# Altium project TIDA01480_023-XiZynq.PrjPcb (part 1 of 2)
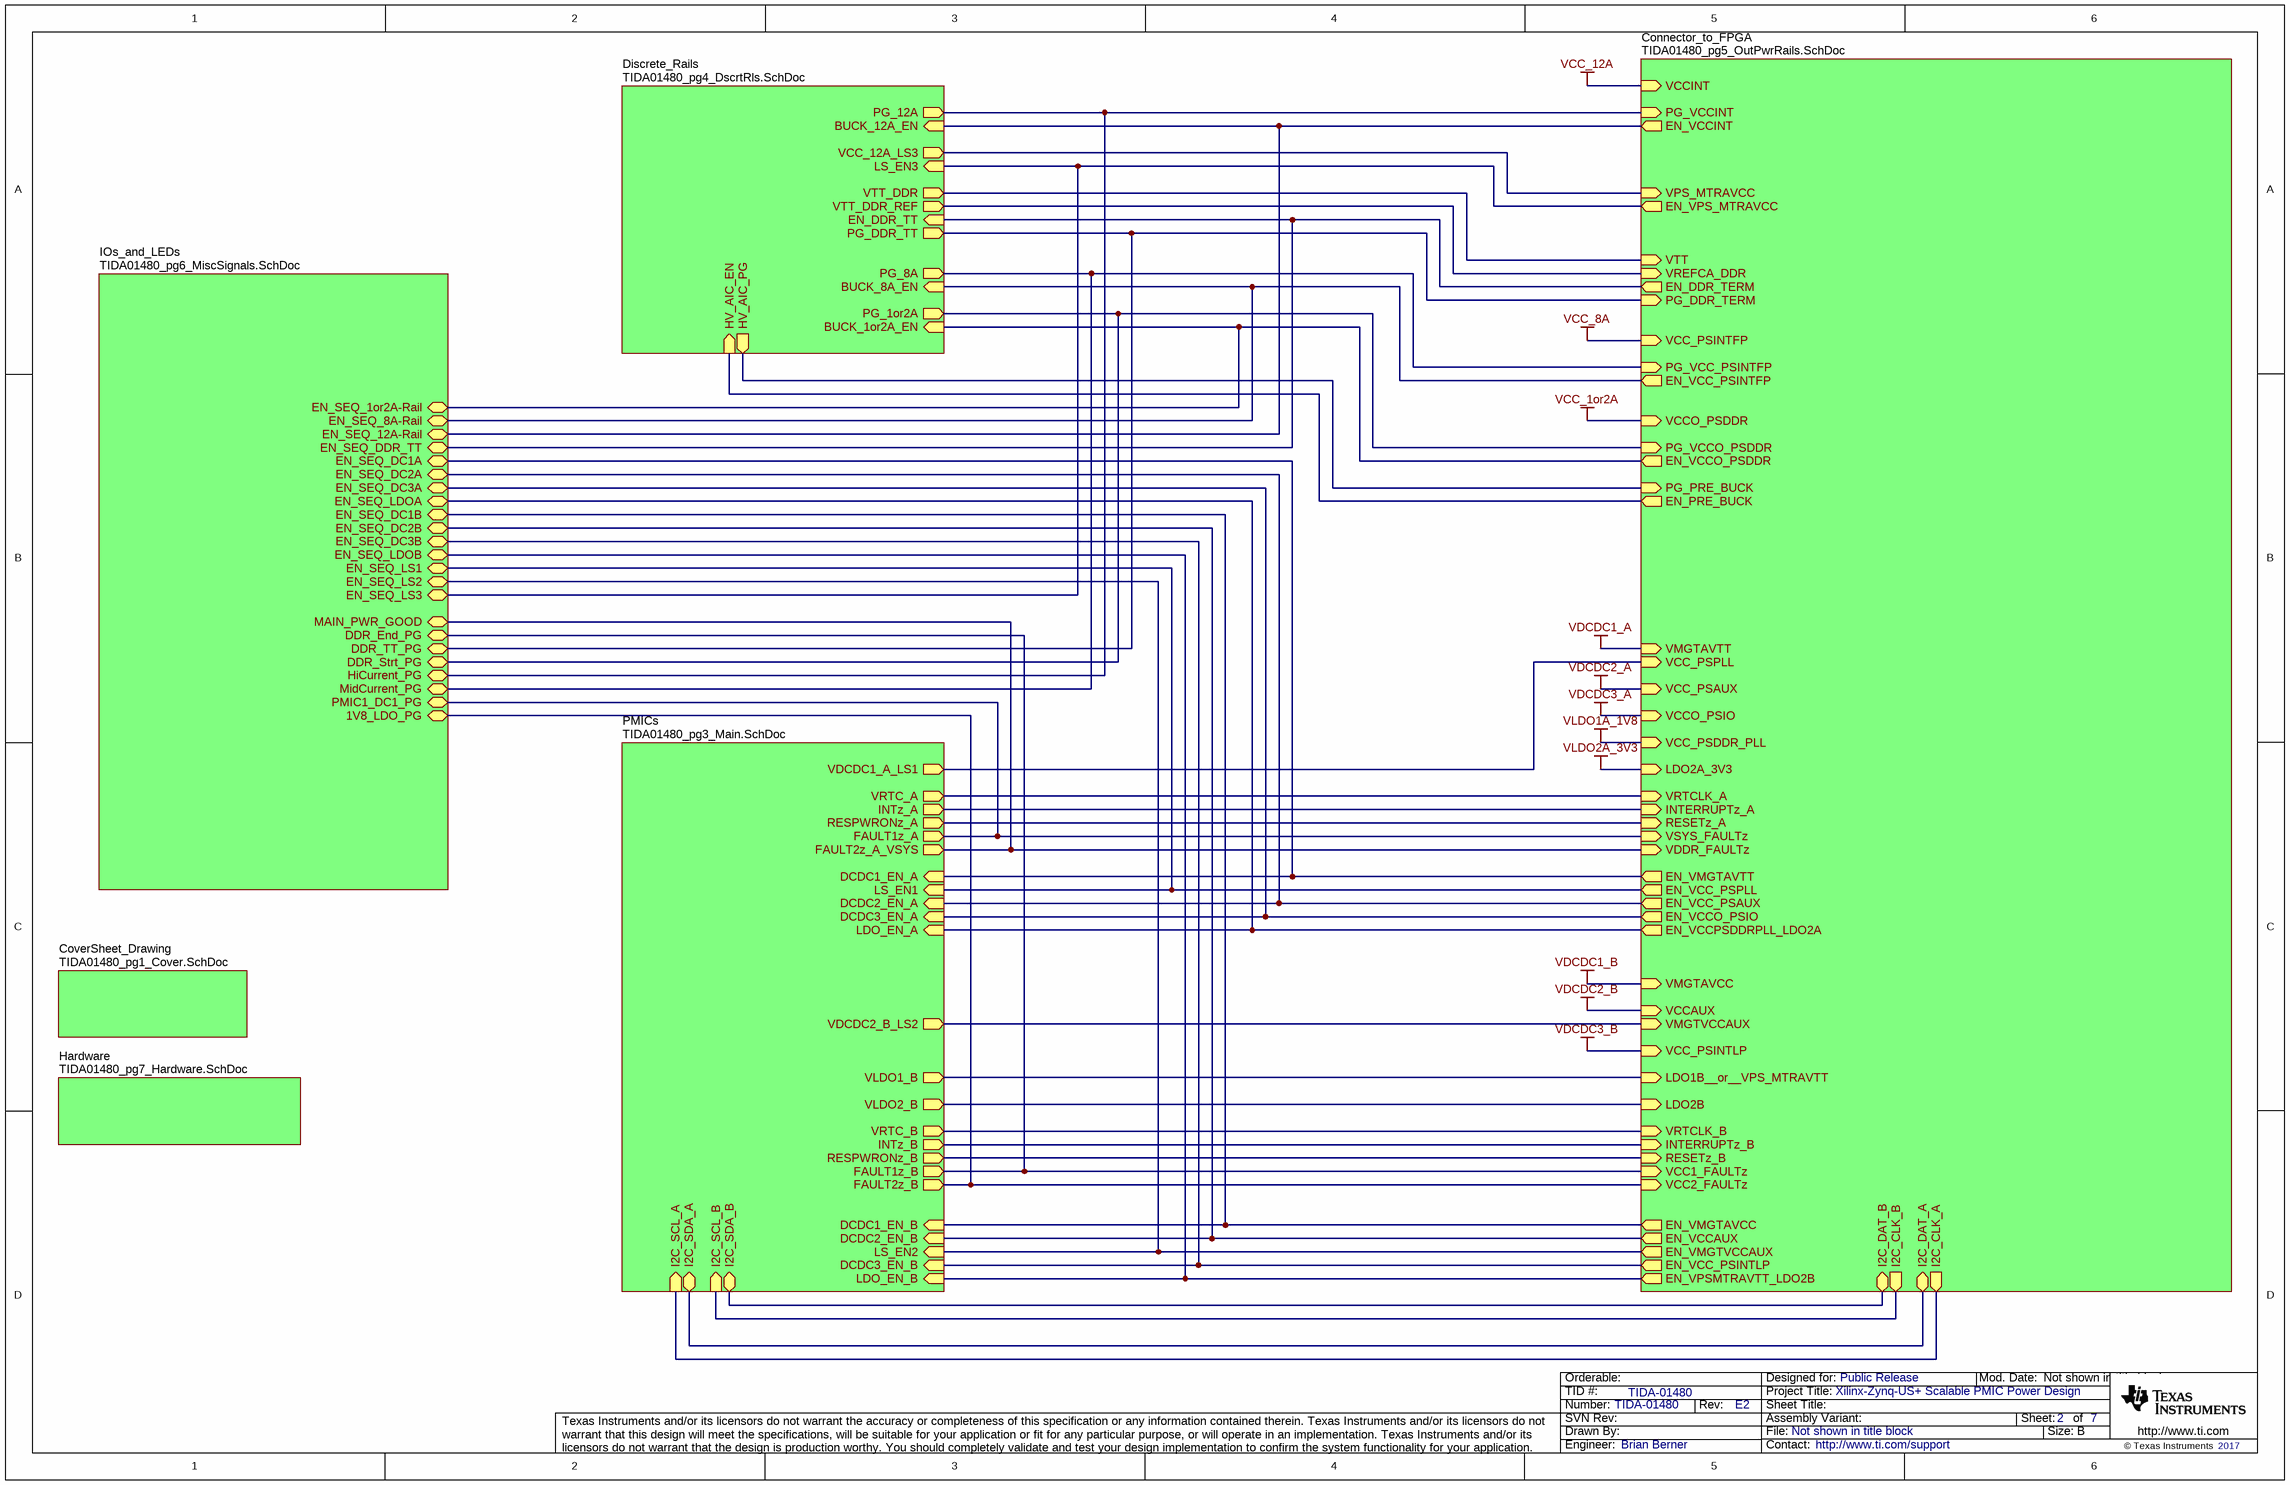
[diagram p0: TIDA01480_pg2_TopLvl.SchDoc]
CopyrightYear: 2017; PCB_Layout: Brian Berner; PCB_Rev: E2; PRJ_Customer: Public Release; PRJ_Engineer: Brian Berner; PRJ_Number: TIDA-01480; PRJ_Title: Xilinx-Zynq-US+ Scalable PMIC Power Design; SCH_Rev: E2; TechSupport: http://www.ti.com/support; TID: TIDA-01480
7 sheets, 333 parts. Net scope: hierarchical (ports join the sheet entries above them; power ports are global).
Board file: TIDA01480_PCB.PcbDoc
Sheets:
  TIDA01480_pg2_TopLvl.SchDoc
    PMICs = TIDA01480_pg3_Main.SchDoc
    Connector_to_FPGA = TIDA01480_pg5_OutPwrRails.SchDoc
    Discrete_Rails = TIDA01480_pg4_DscrtRls.SchDoc
    Hardware = TIDA01480_pg7_Hardware.SchDoc
    CoverSheet_Drawing = TIDA01480_pg1_Cover.SchDoc
    IOs_and_LEDs = TIDA01480_pg6_MiscSignals.SchDoc

## Sheet TIDA01480_pg2_TopLvl.SchDoc
size 431 x 279 mm; Date: Not shown in title block; ApprovedBy: Not shown in title block; CheckedBy: Not shown in title block; Author: Not shown in title block; CompanyName: Not shown in title block; Engineer: Not shown in title block; Organization: Not shown in title block; Address1: Not shown in title block; Address2: Not shown in title block; Address3: Not shown in title block; Address4: Not shown in title block; DocumentNumber: 1; Revision: Use project parameter SCH_Rev; SheetNumber: 2; SheetTotal: 7; PageSetup: Record=PageOptions¦CenterHorizontal=True¦CenterVertical=True¦PrintScale=1.00¦XCorrection=1.00¦YCorrection=1.00¦PrintKind=0¦BorderSize=5000000¦LeftOffset=0¦BottomOffset=0¦Orientation=2¦PaperLength=1000¦PaperWidth=1000¦Scale=100¦PaperSource=15¦PrintQuality=600¦MediaType=1¦DitherType=10¦PaperKind=Letter¦PrintScaleMode=1

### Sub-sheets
Connector_to_FPGA = TIDA01480_pg5_OutPwrRails.SchDoc: VCCINT (in), PG_VCCINT (in), VPS_MTRAVCC (in), VCC_PSINTFP (in), PG_VCC_PSINTFP (in), VCCO_PSDDR (in), PG_VCCO_PSDDR (in), VMGTAVTT (in), VCC_PSPLL (in), VCC_PSAUX (in), VCCO_PSIO (in), VCC_PSDDR_PLL (in), LDO2A_3V3 (in), VMGTAVCC (in), VCCAUX (in), VMGTVCCAUX (in), VCC_PSINTLP (in), LDO1B__or__VPS_MTRAVTT (in), LDO2B (in), INTERRUPTz_A (in), RESETz_A (in), VSYS_FAULTz (in), VDDR_FAULTz (in), INTERRUPTz_B (in), RESETz_B (in), VCC1_FAULTz (in), VCC2_FAULTz (in), EN_VCCINT (out), EN_VPS_MTRAVCC (out), EN_VCC_PSINTFP (out), EN_VCCO_PSDDR (out), EN_VMGTAVTT (out), EN_VCC_PSPLL (out), EN_VCC_PSAUX (out), EN_VCCPSDDRPLL_LDO2A (out), EN_VMGTAVCC (out), EN_VMGTVCCAUX (out), EN_VCCAUX (out), EN_VCC_PSINTLP (out), EN_VPSMTRAVTT_LDO2B (out), EN_VCCO_PSIO (out), VRTCLK_B (in), VRTCLK_A (in), VTT (in), VREFCA_DDR (in), EN_DDR_TERM (out), PG_DDR_TERM (in), I2C_DAT_B (bidir), I2C_CLK_B (out), I2C_DAT_A (bidir), I2C_CLK_A (out), PG_PRE_BUCK (in), EN_PRE_BUCK (out)
CoverSheet_Drawing = TIDA01480_pg1_Cover.SchDoc: no entries
Discrete_Rails = TIDA01480_pg4_DscrtRls.SchDoc: BUCK_12A_EN (in), BUCK_8A_EN (in), BUCK_1or2A_EN (in), PG_12A (out), PG_8A (out), PG_1or2A (out), VCC_12A_LS3 (out), LS_EN3 (in), VTT_DDR (out), VTT_DDR_REF (out), EN_DDR_TT (in), PG_DDR_TT (out), HV_AIC_EN (in), HV_AIC_PG (out)
Hardware = TIDA01480_pg7_Hardware.SchDoc: no entries
IOs_and_LEDs = TIDA01480_pg6_MiscSignals.SchDoc: EN_SEQ_LDOB, EN_SEQ_DC3B, EN_SEQ_DC2B, EN_SEQ_DC1B, EN_SEQ_LDOA, EN_SEQ_DC3A, EN_SEQ_DC2A, EN_SEQ_LS1, EN_SEQ_LS2, EN_SEQ_LS3, MAIN_PWR_GOOD, DDR_TT_PG, DDR_End_PG, DDR_Strt_PG, HiCurrent_PG, MidCurrent_PG, PMIC1_DC1_PG, 1V8_LDO_PG, EN_SEQ_DC1A, EN_SEQ_12A-Rail, EN_SEQ_8A-Rail, EN_SEQ_1or2A-Rail, EN_SEQ_DDR_TT
PMICs = TIDA01480_pg3_Main.SchDoc: INTz_A (out), RESPWRONz_A (out), FAULT1z_A (out), FAULT2z_A_VSYS (out), DCDC1_EN_A (in), DCDC2_EN_A (in), DCDC3_EN_A (in), LDO_EN_A (in), VLDO1_B (out), VLDO2_B (out), INTz_B (out), RESPWRONz_B (out), FAULT1z_B (out), FAULT2z_B (out), DCDC1_EN_B (in), DCDC2_EN_B (in), DCDC3_EN_B (in), LDO_EN_B (in), VDCDC1_A_LS1 (out), VDCDC2_B_LS2 (out), LS_EN1 (in), LS_EN2 (in), I2C_SCL_A (in), I2C_SDA_A (bidir), VRTC_A (out), VRTC_B (out), I2C_SCL_B (in), I2C_SDA_B (bidir)

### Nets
BUCK_1or2A_EN: sheet Connector_to_FPGA/EN_VCCO_PSDDR, sheet Discrete_Rails/BUCK_1or2A_EN, sheet IOs_and_LEDs/EN_SEQ_1or2A-Rail
BUCK_8A_EN: sheet Connector_to_FPGA/EN_VCC_PSINTFP, sheet Discrete_Rails/BUCK_8A_EN, sheet IOs_and_LEDs/EN_SEQ_8A-Rail
BUCK_12A_EN: sheet Connector_to_FPGA/EN_VCCINT, sheet Discrete_Rails/BUCK_12A_EN, sheet IOs_and_LEDs/EN_SEQ_12A-Rail
DCDC1_EN_A: sheet PMICs/DCDC1_EN_A, sheet Connector_to_FPGA/EN_VMGTAVTT, sheet IOs_and_LEDs/EN_SEQ_DC1A
DCDC1_EN_B: sheet PMICs/DCDC1_EN_B, sheet Connector_to_FPGA/EN_VMGTAVCC, sheet IOs_and_LEDs/EN_SEQ_DC1B
DCDC2_EN_A: sheet PMICs/DCDC2_EN_A, sheet Connector_to_FPGA/EN_VCC_PSAUX, sheet IOs_and_LEDs/EN_SEQ_DC2A
DCDC2_EN_B: sheet PMICs/DCDC2_EN_B, sheet Connector_to_FPGA/EN_VCCAUX, sheet IOs_and_LEDs/EN_SEQ_DC2B
DCDC3_EN_A: sheet PMICs/DCDC3_EN_A, sheet Connector_to_FPGA/EN_VCCO_PSIO, sheet IOs_and_LEDs/EN_SEQ_DC3A
DCDC3_EN_B: sheet PMICs/DCDC3_EN_B, sheet Connector_to_FPGA/EN_VCC_PSINTLP, sheet IOs_and_LEDs/EN_SEQ_DC3B
DDR_Strt_PG: sheet Connector_to_FPGA/PG_VCCO_PSDDR, sheet Discrete_Rails/PG_1or2A, sheet IOs_and_LEDs/DDR_Strt_PG
DDR_TT_PG: sheet Connector_to_FPGA/PG_DDR_TERM, sheet Discrete_Rails/PG_DDR_TT, sheet IOs_and_LEDs/DDR_TT_PG
EN_DDR_TERM: sheet Connector_to_FPGA/EN_DDR_TERM, sheet Discrete_Rails/EN_DDR_TT, sheet IOs_and_LEDs/EN_SEQ_DDR_TT
EN_PRE_BUCK: sheet Connector_to_FPGA/EN_PRE_BUCK, sheet Discrete_Rails/HV_AIC_EN
EN_SEQ_LDOA: sheet PMICs/LDO_EN_A, sheet Connector_to_FPGA/EN_VCCPSDDRPLL_LDO2A, sheet IOs_and_LEDs/EN_SEQ_LDOA
EN_SEQ_LDOB: sheet PMICs/LDO_EN_B, sheet Connector_to_FPGA/EN_VPSMTRAVTT_LDO2B, sheet IOs_and_LEDs/EN_SEQ_LDOB
EN_SEQ_LS1: sheet PMICs/LS_EN1, sheet Connector_to_FPGA/EN_VCC_PSPLL, sheet IOs_and_LEDs/EN_SEQ_LS1
EN_SEQ_LS2: sheet PMICs/LS_EN2, sheet Connector_to_FPGA/EN_VMGTVCCAUX, sheet IOs_and_LEDs/EN_SEQ_LS2
EN_SEQ_LS3: sheet Connector_to_FPGA/EN_VPS_MTRAVCC, sheet Discrete_Rails/LS_EN3, sheet IOs_and_LEDs/EN_SEQ_LS3
HiCurrent_PG: sheet Connector_to_FPGA/PG_VCCINT, sheet Discrete_Rails/PG_12A, sheet IOs_and_LEDs/HiCurrent_PG
HV_AIC_PG: sheet Connector_to_FPGA/PG_PRE_BUCK, sheet Discrete_Rails/HV_AIC_PG
I2C_CLK_A: sheet PMICs/I2C_SCL_A, sheet Connector_to_FPGA/I2C_CLK_A
I2C_CLK_B: sheet PMICs/I2C_SCL_B, sheet Connector_to_FPGA/I2C_CLK_B
I2C_DAT_A: sheet PMICs/I2C_SDA_A, sheet Connector_to_FPGA/I2C_DAT_A
I2C_DAT_B: sheet PMICs/I2C_SDA_B, sheet Connector_to_FPGA/I2C_DAT_B
INTERRUPTz_A: sheet PMICs/INTz_A, sheet Connector_to_FPGA/INTERRUPTz_A
INTERRUPTz_B: sheet PMICs/INTz_B, sheet Connector_to_FPGA/INTERRUPTz_B
LDO1B__or__VPS_MTRAVTT: sheet PMICs/VLDO1_B, sheet Connector_to_FPGA/LDO1B__or__VPS_MTRAVTT
LDO2B: sheet PMICs/VLDO2_B, sheet Connector_to_FPGA/LDO2B
LOW_BATz_A: sheet PMICs/FAULT1z_A, sheet Connector_to_FPGA/VSYS_FAULTz, sheet IOs_and_LEDs/PMIC1_DC1_PG
LOW_BATz_B: sheet PMICs/FAULT1z_B, sheet Connector_to_FPGA/VCC1_FAULTz, sheet IOs_and_LEDs/DDR_End_PG
MidCurrent_PG: sheet Connector_to_FPGA/PG_VCC_PSINTFP, sheet Discrete_Rails/PG_8A, sheet IOs_and_LEDs/MidCurrent_PG
PWRFAILz_A: sheet PMICs/FAULT2z_A_VSYS, sheet Connector_to_FPGA/VDDR_FAULTz, sheet IOs_and_LEDs/MAIN_PWR_GOOD
PWRFAILz_B: sheet PMICs/FAULT2z_B, sheet Connector_to_FPGA/VCC2_FAULTz, sheet IOs_and_LEDs/1V8_LDO_PG
RESETz_A: sheet PMICs/RESPWRONz_A, sheet Connector_to_FPGA/RESETz_A
RESETz_B: sheet PMICs/RESPWRONz_B, sheet Connector_to_FPGA/RESETz_B
VCC_12A_LS3: sheet Connector_to_FPGA/VPS_MTRAVCC, sheet Discrete_Rails/VCC_12A_LS3
VCC_PSPLL: sheet PMICs/VDCDC1_A_LS1, sheet Connector_to_FPGA/VCC_PSPLL
VDCDC2_B_LS2: sheet PMICs/VDCDC2_B_LS2, sheet Connector_to_FPGA/VMGTVCCAUX
VREFCA_DDR: sheet Connector_to_FPGA/VREFCA_DDR, sheet Discrete_Rails/VTT_DDR_REF
VRTC_A: sheet PMICs/VRTC_A, sheet Connector_to_FPGA/VRTCLK_A
VRTC_B: sheet PMICs/VRTC_B, sheet Connector_to_FPGA/VRTCLK_B
VTT: sheet Connector_to_FPGA/VTT, sheet Discrete_Rails/VTT_DDR

## Sheet TIDA01480_pg3_Main.SchDoc
size 431 x 279 mm; Date: Not shown in title block; ApprovedBy: Not shown in title block; CheckedBy: Not shown in title block; Author: Not shown in title block; CompanyName: Not shown in title block; Engineer: Not shown in title block; Organization: Not shown in title block; Address1: Not shown in title block; Address2: Not shown in title block; Address3: Not shown in title block; Address4: Not shown in title block; DocumentNumber: 1; Revision: Use project parameter SCH_Rev; SheetNumber: 3; SheetTotal: 7; PageSetup: Record=PageOptions¦CenterHorizontal=True¦CenterVertical=True¦PrintScale=1.00¦XCorrection=1.00¦YCorrection=1.00¦PrintKind=0¦BorderSize=5000000¦LeftOffset=0¦BottomOffset=0¦Orientation=2¦PaperLength=1000¦PaperWidth=1000¦Scale=100¦PaperSource=15¦PrintQuality=600¦MediaType=1¦DitherType=10¦PaperKind=Letter¦PrintScaleMode=1
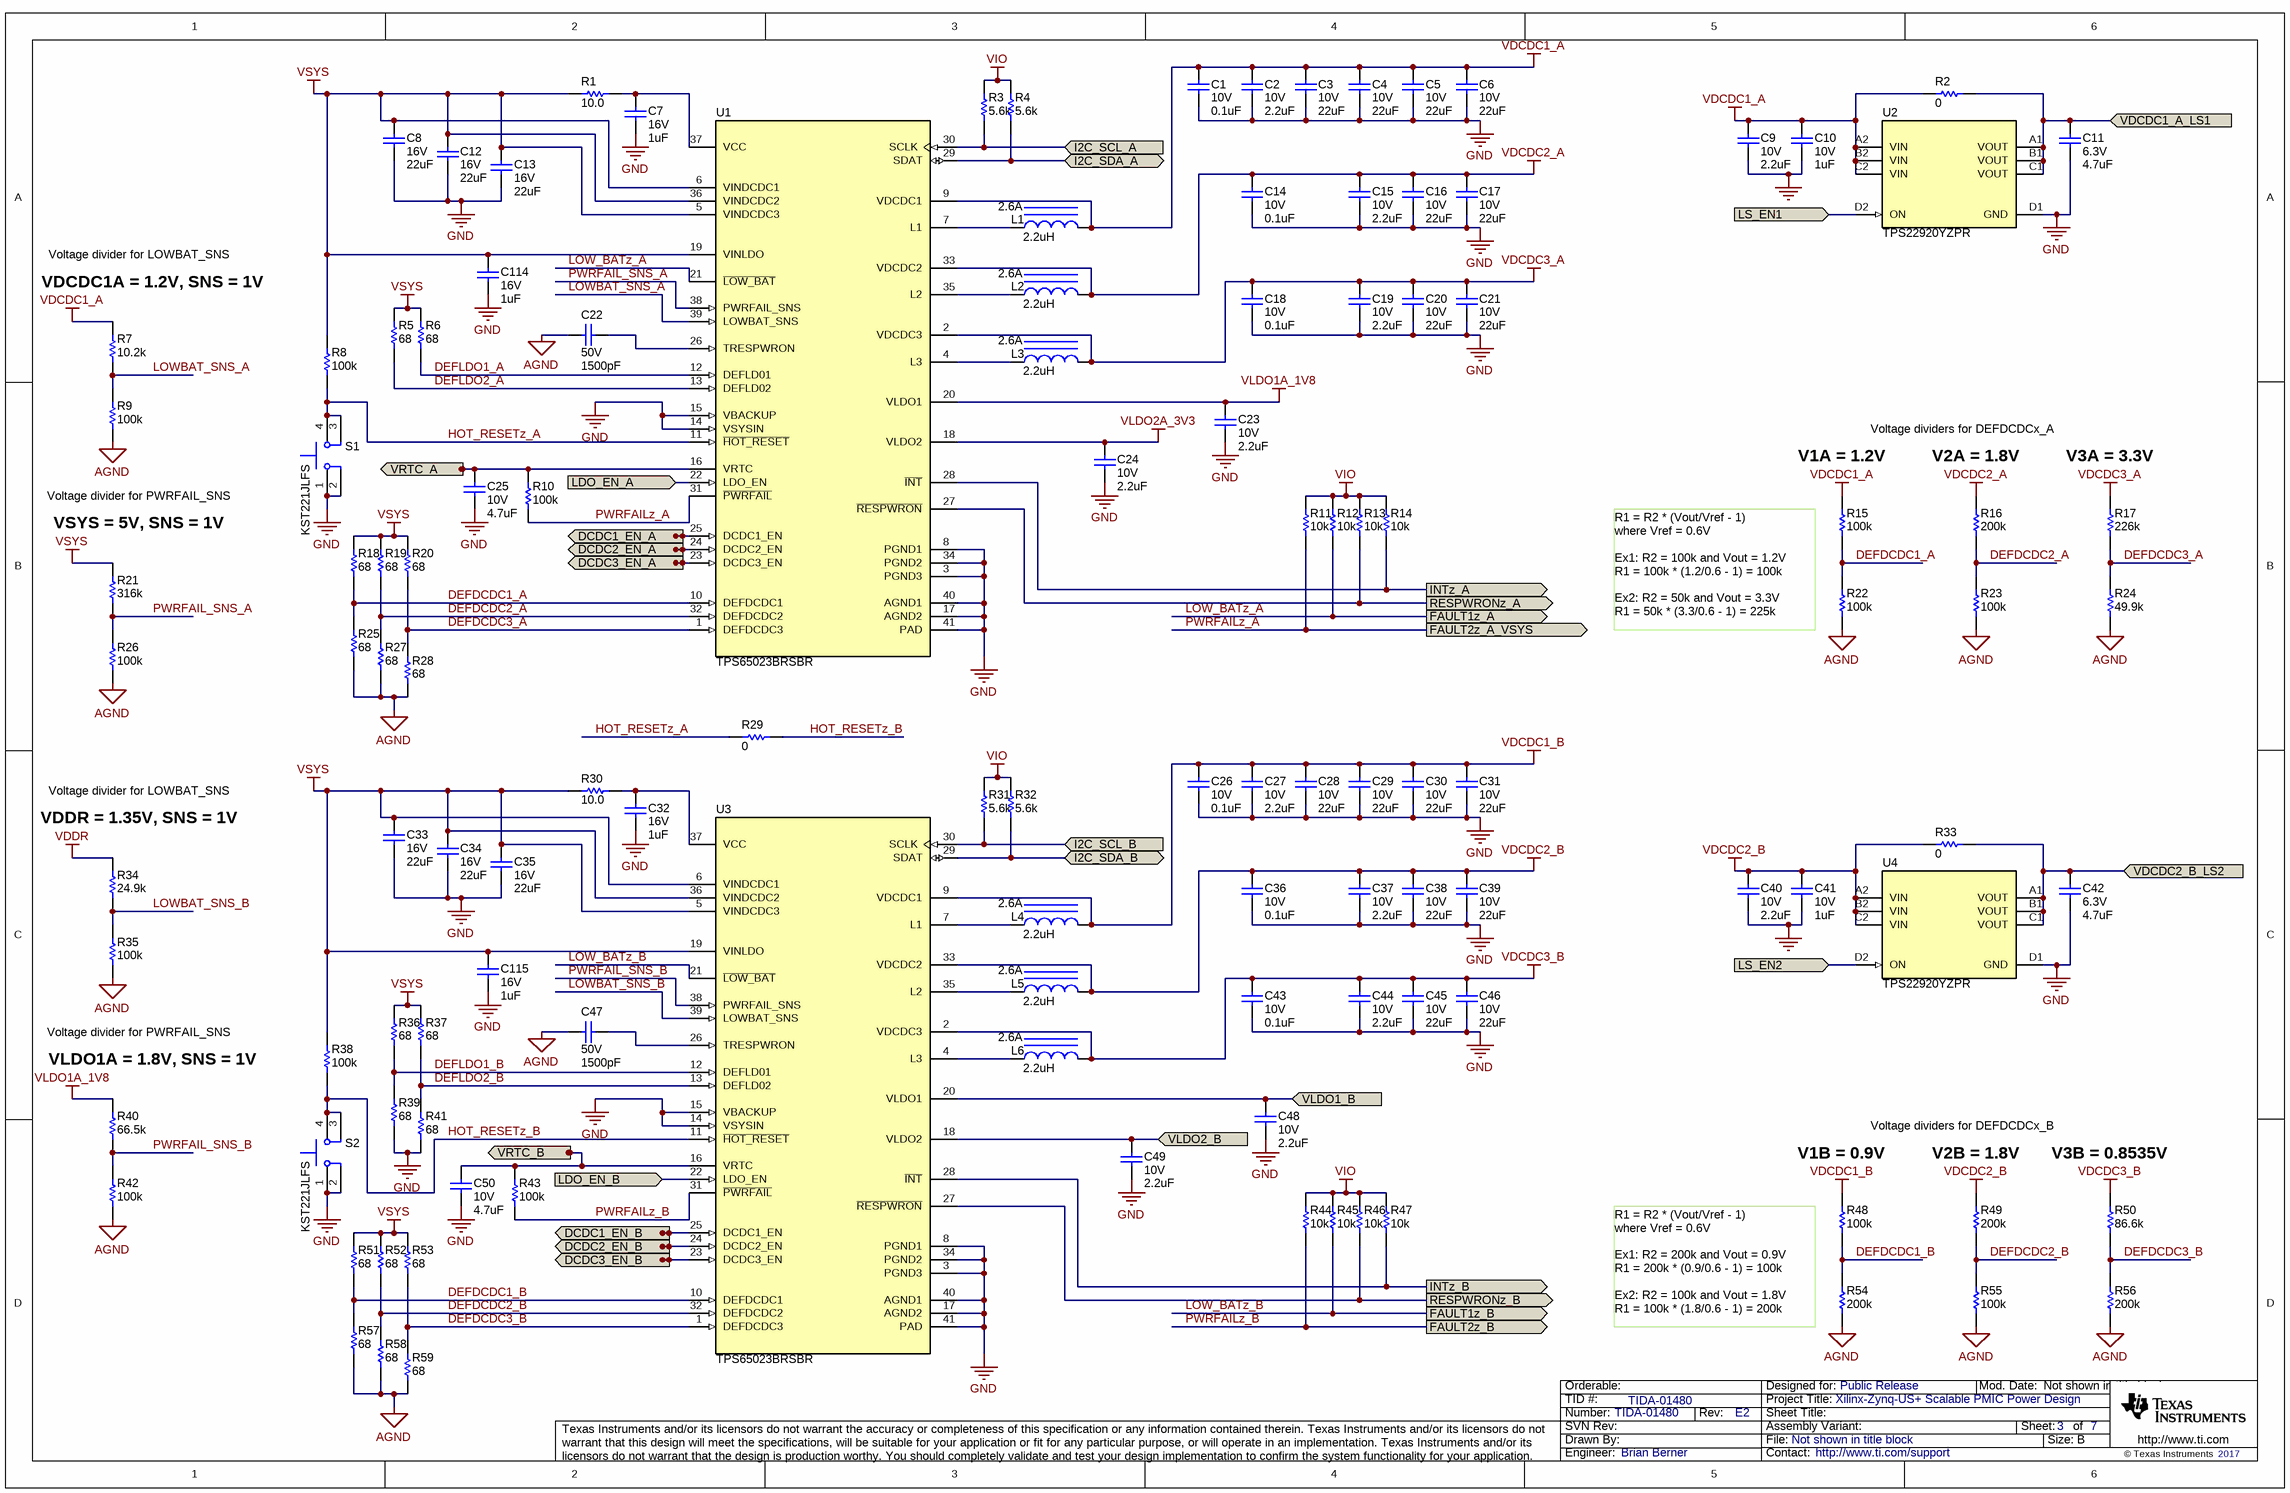
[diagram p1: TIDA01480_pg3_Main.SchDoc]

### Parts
C1  VDC_V: 10V  ValueDisplayed: 0.1uF  [0402]  (hidden comment: GRM155R71A104KA01D)
C2  VDC_V: 10V  ValueDisplayed: 2.2uF  [0603]  (hidden comment: GRM188R71A225KE15D)
C3  VDC_V: 10V  ValueDisplayed: 22uF  [0805_HV]  (hidden comment: C2012X7S1A226M125AC)
C4  VDC_V: 10V  ValueDisplayed: 22uF  [0805_HV]  (hidden comment: C2012X7S1A226M125AC)
C5  VDC_V: 10V  ValueDisplayed: 22uF  [0805_HV]  (hidden comment: C2012X7S1A226M125AC)
C6  VDC_V: 10V  ValueDisplayed: 22uF  [0805_HV]  (hidden comment: C2012X7S1A226M125AC)
C7  VDC_V: 16V  ValueDisplayed: 1uF  [0603]  (hidden comment: 885012106017)
C8  VDC_V: 16V  ValueDisplayed: 22uF  [1210_280]  (hidden comment: C3225X7R1C226K250AC)
C9  VDC_V: 10V  ValueDisplayed: 2.2uF  [0603]  (hidden comment: GRM188R71A225KE15D)
C10  VDC_V: 10V  ValueDisplayed: 1uF  [0402]  (hidden comment: GRM155R61A105ME15D)
C11  VDC_V: 6.3V  ValueDisplayed: 4.7uF  [0603]  (hidden comment: JMK107BB7475MA-T)
C12  VDC_V: 16V  ValueDisplayed: 22uF  [1210_280]  (hidden comment: C3225X7R1C226K250AC)
C13  VDC_V: 16V  ValueDisplayed: 22uF  [1210_280]  (hidden comment: C3225X7R1C226K250AC)
C14  VDC_V: 10V  ValueDisplayed: 0.1uF  [0402]  (hidden comment: GRM155R71A104KA01D)
C15  VDC_V: 10V  ValueDisplayed: 2.2uF  [0603]  (hidden comment: GRM188R71A225KE15D)
C16  VDC_V: 10V  ValueDisplayed: 22uF  [0805_HV]  (hidden comment: C2012X7S1A226M125AC)
C17  VDC_V: 10V  ValueDisplayed: 22uF  [0805_HV]  (hidden comment: C2012X7S1A226M125AC)
C18  VDC_V: 10V  ValueDisplayed: 0.1uF  [0402]  (hidden comment: GRM155R71A104KA01D)
C19  VDC_V: 10V  ValueDisplayed: 2.2uF  [0603]  (hidden comment: GRM188R71A225KE15D)
C20  VDC_V: 10V  ValueDisplayed: 22uF  [0805_HV]  (hidden comment: C2012X7S1A226M125AC)
C21  VDC_V: 10V  ValueDisplayed: 22uF  [0805_HV]  (hidden comment: C2012X7S1A226M125AC)
C22  VDC_V: 50V  ValueDisplayed: 1500pF  [0402]  (hidden comment: GRM155R71H152KA01D)
C23  VDC_V: 10V  ValueDisplayed: 2.2uF  [0603]  (hidden comment: GRM188R71A225KE15D)
C24  VDC_V: 10V  ValueDisplayed: 2.2uF  [0603]  (hidden comment: GRM188R71A225KE15D)
C25  VDC_V: 10V  ValueDisplayed: 4.7uF  [0805_HV]  (hidden comment: 885012207025)
C26  VDC_V: 10V  ValueDisplayed: 0.1uF  [0402]  (hidden comment: GRM155R71A104KA01D)
C27  VDC_V: 10V  ValueDisplayed: 2.2uF  [0603]  (hidden comment: GRM188R71A225KE15D)
C28  VDC_V: 10V  ValueDisplayed: 22uF  [0805_HV]  (hidden comment: C2012X7S1A226M125AC)
C29  VDC_V: 10V  ValueDisplayed: 22uF  [0805_HV]  (hidden comment: C2012X7S1A226M125AC)
C30  VDC_V: 10V  ValueDisplayed: 22uF  [0805_HV]  (hidden comment: C2012X7S1A226M125AC)
C31  VDC_V: 10V  ValueDisplayed: 22uF  [0805_HV]  (hidden comment: C2012X7S1A226M125AC)
C32  VDC_V: 16V  ValueDisplayed: 1uF  [0603]  (hidden comment: 885012106017)
C33  VDC_V: 16V  ValueDisplayed: 22uF  [1210_280]  (hidden comment: C3225X7R1C226K250AC)
C34  VDC_V: 16V  ValueDisplayed: 22uF  [1210_280]  (hidden comment: C3225X7R1C226K250AC)
C35  VDC_V: 16V  ValueDisplayed: 22uF  [1210_280]  (hidden comment: C3225X7R1C226K250AC)
C36  VDC_V: 10V  ValueDisplayed: 0.1uF  [0402]  (hidden comment: GRM155R71A104KA01D)
C37  VDC_V: 10V  ValueDisplayed: 2.2uF  [0603]  (hidden comment: GRM188R71A225KE15D)
C38  VDC_V: 10V  ValueDisplayed: 22uF  [0805_HV]  (hidden comment: C2012X7S1A226M125AC)
C39  VDC_V: 10V  ValueDisplayed: 22uF  [0805_HV]  (hidden comment: C2012X7S1A226M125AC)
C40  VDC_V: 10V  ValueDisplayed: 2.2uF  [0603]  (hidden comment: GRM188R71A225KE15D)
C41  VDC_V: 10V  ValueDisplayed: 1uF  [0402]  (hidden comment: GRM155R61A105ME15D)
C42  VDC_V: 6.3V  ValueDisplayed: 4.7uF  [0603]  (hidden comment: JMK107BB7475MA-T)
C43  VDC_V: 10V  ValueDisplayed: 0.1uF  [0402]  (hidden comment: GRM155R71A104KA01D)
C44  VDC_V: 10V  ValueDisplayed: 2.2uF  [0603]  (hidden comment: GRM188R71A225KE15D)
C45  VDC_V: 10V  ValueDisplayed: 22uF  [0805_HV]  (hidden comment: C2012X7S1A226M125AC)
C46  VDC_V: 10V  ValueDisplayed: 22uF  [0805_HV]  (hidden comment: C2012X7S1A226M125AC)
C47  VDC_V: 50V  ValueDisplayed: 1500pF  [0402]  (hidden comment: GRM155R71H152KA01D)
C48  VDC_V: 10V  ValueDisplayed: 2.2uF  [0603]  (hidden comment: GRM188R71A225KE15D)
C49  VDC_V: 10V  ValueDisplayed: 2.2uF  [0603]  (hidden comment: GRM188R71A225KE15D)
C50  VDC_V: 10V  ValueDisplayed: 4.7uF  [0805_HV]  (hidden comment: 885012207025)
C114  VDC_V: 16V  ValueDisplayed: 1uF  [0603]  (hidden comment: 885012106017)
C115  VDC_V: 16V  ValueDisplayed: 1uF  [0603]  (hidden comment: 885012106017)
L1  Imax_A: 2.6A  ValueDisplayed: 2.2uH  [TFM252012]  (hidden comment: TFM252012ALMA2R2MTAA)
L2  Imax_A: 2.6A  ValueDisplayed: 2.2uH  [TFM252012]  (hidden comment: TFM252012ALMA2R2MTAA)
L3  Imax_A: 2.6A  ValueDisplayed: 2.2uH  [TFM252012]  (hidden comment: TFM252012ALMA2R2MTAA)
L4  Imax_A: 2.6A  ValueDisplayed: 2.2uH  [TFM252012]  (hidden comment: TFM252012ALMA2R2MTAA)
L5  Imax_A: 2.6A  ValueDisplayed: 2.2uH  [TFM252012]  (hidden comment: TFM252012ALMA2R2MTAA)
L6  Imax_A: 2.6A  ValueDisplayed: 2.2uH  [TFM252012]  (hidden comment: TFM252012ALMA2R2MTAA)
R1  ValueDisplayed: 10.0  [0402]  (hidden comment: CRCW040210R0FKED)
R2  ValueDisplayed: 0  [1206]  (hidden comment: CRCW12060000Z0EA)
R3  ValueDisplayed: 5.6k  [0402]  (hidden comment: CRCW04025K60JNED)
R4  ValueDisplayed: 5.6k  [0402]  (hidden comment: CRCW04025K60JNED)
R5  ValueDisplayed: 68  [0402]  (hidden comment: CRCW040268R0JNED)
R6  ValueDisplayed: 68  [0402]  (hidden comment: CRCW040268R0JNED)
R7  ValueDisplayed: 10.2k  [0402]  (hidden comment: CRCW040210K2FKED)
R8  ValueDisplayed: 100k  [0402]  (hidden comment: CRCW0402100KJNED)
R9  ValueDisplayed: 100k  [0402]  (hidden comment: RG1005P-104-B-T5)
R10  ValueDisplayed: 100k  [0402]  (hidden comment: CRCW0402100KJNED)
R11  ValueDisplayed: 10k  [0402]  (hidden comment: CRCW040210K0JNED)
R12  ValueDisplayed: 10k  [0402]  (hidden comment: CRCW040210K0JNED)
R13  ValueDisplayed: 10k  [0402]  (hidden comment: CRCW040210K0JNED)
R14  ValueDisplayed: 10k  [0402]  (hidden comment: CRCW040210K0JNED)
R15  ValueDisplayed: 100k  [0402]  (hidden comment: RG1005P-104-B-T5)
R16  ValueDisplayed: 200k  [0402]  (hidden comment: CRCW0402200KFKED)
R17  ValueDisplayed: 226k  [0402]  (hidden comment: CRCW0402226KFKED)
R18  ValueDisplayed: 68  [0402]  (hidden comment: CRCW040268R0JNED)
R19  ValueDisplayed: 68  [0402]  (hidden comment: CRCW040268R0JNED)
R20  ValueDisplayed: 68  [0402]  (hidden comment: CRCW040268R0JNED)
R21  ValueDisplayed: 316k  [0402]  (hidden comment: CRCW0402316KFKED)
R22  ValueDisplayed: 100k  [0402]  (hidden comment: RG1005P-104-B-T5)
R23  ValueDisplayed: 100k  [0402]  (hidden comment: RG1005P-104-B-T5)
R24  ValueDisplayed: 49.9k  [0402]  (hidden comment: ERJ-2RKF4992X)
R25  ValueDisplayed: 68  [0402]  (hidden comment: CRCW040268R0JNED)
R26  ValueDisplayed: 100k  [0402]  (hidden comment: RG1005P-104-B-T5)
R27  ValueDisplayed: 68  [0402]  (hidden comment: CRCW040268R0JNED)
R28  ValueDisplayed: 68  [0402]  (hidden comment: CRCW040268R0JNED)
R29  ValueDisplayed: 0  [0402]  (hidden comment: CRCW04020000Z0ED)
R30  ValueDisplayed: 10.0  [0402]  (hidden comment: CRCW040210R0FKED)
R31  ValueDisplayed: 5.6k  [0402]  (hidden comment: CRCW04025K60JNED)
R32  ValueDisplayed: 5.6k  [0402]  (hidden comment: CRCW04025K60JNED)
R33  ValueDisplayed: 0  [1206]  (hidden comment: CRCW12060000Z0EA)
R34  ValueDisplayed: 24.9k  [0402]  (hidden comment: CRCW040224K9FKED)
R35  ValueDisplayed: 100k  [0402]  (hidden comment: RG1005P-104-B-T5)
R36  ValueDisplayed: 68  [0402]  (hidden comment: CRCW040268R0JNED)
R37  ValueDisplayed: 68  [0402]  (hidden comment: CRCW040268R0JNED)
R38  ValueDisplayed: 100k  [0402]  (hidden comment: CRCW0402100KJNED)
R39  ValueDisplayed: 68  [0402]  (hidden comment: CRCW040268R0JNED)
R40  ValueDisplayed: 66.5k  [0402]  (hidden comment: CRCW040266K5FKED)
R41  ValueDisplayed: 68  [0402]  (hidden comment: CRCW040268R0JNED)
R42  ValueDisplayed: 100k  [0402]  (hidden comment: RG1005P-104-B-T5)
R43  ValueDisplayed: 100k  [0402]  (hidden comment: CRCW0402100KJNED)
R44  ValueDisplayed: 10k  [0402]  (hidden comment: CRCW040210K0JNED)
R45  ValueDisplayed: 10k  [0402]  (hidden comment: CRCW040210K0JNED)
R46  ValueDisplayed: 10k  [0402]  (hidden comment: CRCW040210K0JNED)
R47  ValueDisplayed: 10k  [0402]  (hidden comment: CRCW040210K0JNED)
R48  ValueDisplayed: 100k  [0402]  (hidden comment: RG1005P-104-B-T5)
R49  ValueDisplayed: 200k  [0402]  (hidden comment: CRCW0402200KFKED)
R50  ValueDisplayed: 86.6k  [0402]  (hidden comment: ERA-2AEB8662X)
R51  ValueDisplayed: 68  [0402]  (hidden comment: CRCW040268R0JNED)
R52  ValueDisplayed: 68  [0402]  (hidden comment: CRCW040268R0JNED)
R53  ValueDisplayed: 68  [0402]  (hidden comment: CRCW040268R0JNED)
R54  ValueDisplayed: 200k  [0402]  (hidden comment: CRCW0402200KFKED)
R55  ValueDisplayed: 100k  [0402]  (hidden comment: RG1005P-104-B-T5)
R56  ValueDisplayed: 200k  [0402]  (hidden comment: CRCW0402200KFKED)
R57  ValueDisplayed: 68  [0402]  (hidden comment: CRCW040268R0JNED)
R58  ValueDisplayed: 68  [0402]  (hidden comment: CRCW040268R0JNED)
R59  ValueDisplayed: 68  [0402]  (hidden comment: CRCW040268R0JNED)
S1  KST221JLFS  [SW_KST221JLFS]
S2  KST221JLFS  [SW_KST221JLFS]
U1  TPS65023BRSBR  [RSB0040B]
U2  TPS22920YZPR  [YZP0008ADCD]
U3  TPS65023BRSBR  [RSB0040B]
U4  TPS22920YZPR  [YZP0008ADCD]

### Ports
DCDC1_EN_A (in), DCDC1_EN_B (in), DCDC2_EN_A (in), DCDC2_EN_B (in), DCDC3_EN_A (in), DCDC3_EN_B (in), FAULT1z_A (out), FAULT1z_B (out), FAULT2z_A_VSYS (out), FAULT2z_B (out), I2C_SCL_A (in), I2C_SCL_B (in), I2C_SDA_A (bidir), I2C_SDA_B (bidir), INTz_A (out), INTz_B (out), LDO_EN_A (in), LDO_EN_B (in), LS_EN1 (in), LS_EN2 (in), RESPWRONz_A (out), RESPWRONz_B (out), VDCDC1_A_LS1, VDCDC2_B_LS2, VLDO1_B, VLDO2_B, VRTC_A, VRTC_B

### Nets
AGND: C22.2 C47.2 R9.1 R22.1 R23.1 R24.1 R25.1 R26.1 R27.1 R28.1 R35.1 R42.1 R54.1 R55.1 R56.1 R57.1 R58.1 R59.1
GND: C1.2 C2.2 C3.2 C4.2 C5.2 C6.2 C7.2 C8.2 C9.2 C10.2 C11.2 C12.2 C13.2 C14.2 C15.2 C16.2 C17.2 C18.2 C19.2 C20.2 C21.2 C23.2 C24.2 C25.2 C26.2 C27.2 C28.2 C29.2 C30.2 C31.2 C32.2 C33.2 C34.2 C35.2 C36.2 C37.2 C38.2 C39.2 C40.2 C41.2 C42.2 C43.2 C44.2 C45.2 C46.2 C48.2 C49.2 C50.2 C114.2 C115.2 R39.1 R41.1 S1.1 S1.2 S2.1 S2.2 U1.3(PGND3) U1.8(PGND1) U1.14(VSYSIN) U1.15(VBACKUP) U1.17(AGND2) U1.34(PGND2) U1.40(AGND1) U1.41(PAD) U2.D1(GND) U3.3(PGND3) U3.8(PGND1) U3.14(VSYSIN) U3.15(VBACKUP) U3.17(AGND2) U3.34(PGND2) U3.40(AGND1) U3.41(PAD) U4.D1(GND)
VDCDC1_A: C1.1 C2.1 C3.1 C4.1 C5.1 C6.1 C9.1 C10.1 L1.2 R2.1 R7.2 R15.2 U1.9(VDCDC1) U2.A2(VIN) U2.B2(VIN) U2.C2(VIN)
VDCDC1_B: C26.1 C27.1 C28.1 C29.1 C30.1 C31.1 L4.2 R48.2 U3.9(VDCDC1)
VDCDC2_A: C14.1 C15.1 C16.1 C17.1 L2.2 R16.2 U1.33(VDCDC2)
VDCDC2_B: C36.1 C37.1 C38.1 C39.1 C40.1 C41.1 L5.2 R33.1 R49.2 U3.33(VDCDC2) U4.A2(VIN) U4.B2(VIN) U4.C2(VIN)
VDCDC3_A: C18.1 C19.1 C20.1 C21.1 L3.2 R17.2 U1.2(VDCDC3)
VDCDC3_B: C43.1 C44.1 C45.1 C46.1 L6.2 R50.2 U3.2(VDCDC3)
VDDR: R34.2
VIO: R3.2 R4.2 R11.2 R12.2 R13.2 R14.2 R31.2 R32.2 R44.2 R45.2 R46.2 R47.2
VLDO1A_1V8: C23.1 R40.2 U1.20(VLDO1)
VLDO2A_3V3: C24.1 U1.18(VLDO2)
VSYS: C8.1 C12.1 C13.1 C33.1 C34.1 C35.1 C114.1 C115.1 R1.1 R5.2 R6.2 R8.2 R18.2 R19.2 R20.2 R21.2 R30.1 R36.2 R37.2 R38.2 R51.2 R52.2 R53.2 U1.5(VINDCDC3) U1.6(VINDCDC1) U1.19(VINLDO) U1.36(VINDCDC2) U3.5(VINDCDC3) U3.6(VINDCDC1) U3.19(VINLDO) U3.36(VINDCDC2)
DCDC1_EN_A: U1.25(DCDC1_EN) ; port DCDC1_EN_A
DCDC1_EN_B: U3.25(DCDC1_EN) ; port DCDC1_EN_B
DCDC2_EN_A: U1.24(DCDC2_EN) ; port DCDC2_EN_A
DCDC2_EN_B: U3.24(DCDC2_EN) ; port DCDC2_EN_B
DCDC3_EN_A: U1.23(DCDC3_EN) ; port DCDC3_EN_A
DCDC3_EN_B: U3.23(DCDC3_EN) ; port DCDC3_EN_B
DEFDCDC1_A: R15.1 R18.1 R22.2 R25.2 U1.10(DEFDCDC1)
DEFDCDC1_B: R48.1 R51.1 R54.2 R57.2 U3.10(DEFDCDC1)
DEFDCDC2_A: R16.1 R19.1 R23.2 R27.2 U1.32(DEFDCDC2)
DEFDCDC2_B: R49.1 R52.1 R55.2 R58.2 U3.32(DEFDCDC2)
DEFDCDC3_A: R17.1 R20.1 R24.2 R28.2 U1.1(DEFDCDC3)
DEFDCDC3_B: R50.1 R53.1 R56.2 R59.2 U3.1(DEFDCDC3)
DEFLDO1_A: R6.1 U1.12(DEFLD01)
DEFLDO1_B: R36.1 R39.2 U3.12(DEFLD01)
DEFLDO2_A: R5.1 U1.13(DEFLD02)
DEFLDO2_B: R37.1 R41.2 U3.13(DEFLD02)
EN_SEQ_LDOA: U1.22(LDO_EN) ; port LDO_EN_A
EN_SEQ_LDOB: U3.22(LDO_EN) ; port LDO_EN_B
EN_SEQ_LS1: U2.D2(ON) ; port LS_EN1
EN_SEQ_LS2: U4.D2(ON) ; port LS_EN2
HOT_RESETz_A: R8.1 R29.2 S1.3 S1.4 U1.11(~{HOT_RESET})
HOT_RESETz_B: R29.1 R38.1 S2.3 S2.4 U3.11(~{HOT_RESET})
I2C_CLK_A: R3.1 U1.30(SCLK) ; port I2C_SCL_A
I2C_CLK_B: R31.1 U3.30(SCLK) ; port I2C_SCL_B
I2C_DAT_A: R4.1 U1.29(SDAT) ; port I2C_SDA_A
I2C_DAT_B: R32.1 U3.29(SDAT) ; port I2C_SDA_B
INTERRUPTz_A: R14.1 U1.28(~{INT}) ; port INTz_A
INTERRUPTz_B: R47.1 U3.28(~{INT}) ; port INTz_B
LDO1B__or__VPS_MTRAVTT: C48.1 U3.20(VLDO1) ; port VLDO1_B
LDO2B: C49.1 U3.18(VLDO2) ; port VLDO2_B
LOW_BATz_A: R12.1 U1.21(~{LOW_BAT}) ; port FAULT1z_A
LOW_BATz_B: R45.1 U3.21(~{LOW_BAT}) ; port FAULT1z_B
LOWBAT_SNS_A: R7.1 R9.2 U1.39(LOWBAT_SNS)
LOWBAT_SNS_B: R34.1 R35.2 U3.39(LOWBAT_SNS)
PWRFAIL_SNS_A: R21.1 R26.2 U1.38(PWRFAIL_SNS)
PWRFAIL_SNS_B: R40.1 R42.2 U3.38(PWRFAIL_SNS)
PWRFAILz_A: R10.2 R11.1 U1.31(~{PWRFAIL}) ; port FAULT2z_A_VSYS
PWRFAILz_B: R43.2 R44.1 U3.31(~{PWRFAIL}) ; port FAULT2z_B
RESETz_A: R13.1 U1.27(~{RESPWRON}) ; port RESPWRONz_A
RESETz_B: R46.1 U3.27(~{RESPWRON}) ; port RESPWRONz_B
VCC_PSPLL: C11.1 R2.2 U2.A1(VOUT) U2.B1(VOUT) U2.C1(VOUT) ; port VDCDC1_A_LS1
VDCDC2_B_LS2: C42.1 R33.2 U4.A1(VOUT) U4.B1(VOUT) U4.C1(VOUT) ; port VDCDC2_B_LS2
VRTC_A: C25.1 R10.1 U1.16(VRTC) ; port VRTC_A
VRTC_B: C50.1 R43.1 U3.16(VRTC) ; port VRTC_B
NetC7_1: C7.1 R1.2 U1.37(VCC)
NetC22_1: C22.1 U1.26(TRESPWRON)
NetC32_1: C32.1 R30.2 U3.37(VCC)
NetC47_1: C47.1 U3.26(TRESPWRON)
NetL1_1: L1.1 U1.7(L1)
NetL2_1: L2.1 U1.35(L2)
NetL3_1: L3.1 U1.4(L3)
NetL4_1: L4.1 U3.7(L1)
NetL5_1: L5.1 U3.35(L2)
NetL6_1: L6.1 U3.4(L3)

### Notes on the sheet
- Voltage divider for LOWBAT_SNS
- (near R7) VDCDC1A = 1.2V, SNS = 1V
- Voltage dividers for DEFDCDCx_A
- Voltage divider for PWRFAIL_SNS
- (near R15) V1A = 1.2V
- (near R16) V2A = 1.8V
- (near R17) V3A = 3.3V
- (near R21) VSYS = 5V, SNS = 1V
- R1 = R2 * (Vout/Vref - 1)
  where Vref = 0.6V
  Ex1: R2 = 100k and Vout = 1.2V
  R1 = 100k * (1.2/0.6 - 1) = 100k
  Ex2: R2 = 50k and Vout = 3.3V
  R1 = 50k * (3.3/0.6 - 1) = 225k
- (near R34) VDDR = 1.35V, SNS = 1V
- (near R40) VLDO1A = 1.8V, SNS = 1V
- (near R48) V1B = 0.9V
- Voltage dividers for DEFDCDCx_B
- (near R49) V2B = 1.8V
- (near R50) V3B = 0.8535V
- R1 = R2 * (Vout/Vref - 1)
  where Vref = 0.6V
  Ex1: R2 = 200k and Vout = 0.9V
  R1 = 200k * (0.9/0.6 - 1) = 100k
  Ex2: R2 = 100k and Vout = 1.8V
  R1 = 100k * (1.8/0.6 - 1) = 200k

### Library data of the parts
C1 C14 C18 C26 C36 C43 = CMP-0006629-2: CAP, CERM, 0.1 uF, 10 V, +/- 10%, X7R, 0402; Manufacturer: MuRata; TaMin_C: -55°C; Polarized: N; SizeAreaWB_mm2: 3; Value1: Unknown; U/M: EA; Value: 0.1uF; TaMax_C: 125°C; SizeZ_mm: 0.6; SizeX_mm: 1; SizeY_mm: 0.5; Cap_F: 100nF; AEC Category: Q200
C2 C9 C15 C19 C23 C24 C27 C37 C40 C44 C48 C49 = CMP-0007370-3: CAP, CERM, 2.2 uF, 10 V, +/- 10%, X7R, 0603; Manufacturer: MuRata; TaMin_C: -55°C; ESR_ohm: 9m; Polarized: N; SizeAreaWB_mm2: 4.68; Value1: 0.009 ohm; U/M: EA; Value: 2.2uF; TaMax_C: 125°C; SizeZ_mm: 1; SizeX_mm: 1.6; SizeY_mm: 0.8; SizeArea_mm2: 1.28; Cap_F: 2.2µF; AEC Category: Q200
C3-C6 C16 C17 C20 C21 C28-C31 C38 C39 C45 C46 = CMP-0007890-2: CAP, CERM, 22 uF, 10 V, +/- 20%, X7S, 0805; Manufacturer: TDK; TaMin_C: -55°C; ESR_ohm: 2.05m; Polarized: N; SizeAreaWB_mm2: 6.75; Value1: 0.00205 ohm; U/M: EA; Value: 22uF; TaMax_C: 125°C; SizeZ_mm: 1.45; SizeX_mm: 2; SizeY_mm: 1.25; Cap_Case: 0805; SizeArea_mm2: 2.5; Cap_F: 22µF; IRMS_A: 4.55587A; AEC Category: Q200
C7 C32 C114 C115 = CMP-0006824-2: CAP, CERM, 1 uF, 16 V, +/- 20%, X5R, 0603; Manufacturer: Wurth Elektronik; TaMin_C: -55°C; Polarized: N; SizeAreaWB_mm2: 4.68; Value1: Unknown; U/M: EA; Value: 1uF; TaMax_C: 85°C; SizeZ_mm: 1; SizeX_mm: 1.6; SizeY_mm: 0.8; SizeArea_mm2: 1.28; Cap_F: 1µF; AEC Category: Q200
C8 C12 C13 C33-C35 = CMP-0009116-1: CAP, CERM, 22 uF, 16 V, +/- 10%, X7R, 1210; Manufacturer: TDK; TaMin_C: -55°C; ESR_ohm: 2.582m; Polarized: N; SizeAreaWB_mm2: 14.7; Value1: 0.002582 ohm; U/M: EA; Value: 22uF; TaMax_C: 125°C; SizeZ_mm: 2.8; SizeX_mm: 3.2; SizeY_mm: 2.5; SizeArea_mm2: 8; Cap_F: 22µF; IRMS_A: 4.57562A; AEC Category: Q200
C10 C41 = CMP-0064927-2: CAP, CERM, 1 uF, 10 V,+/- 20%, X5R, 0402; Manufacturer: MuRata; TaMin_C: -55°C; Polarized: N; SizeAreaWB_mm2: 3; Value1: Unknown; U/M: EA; Value: 1uF; TaMax_C: 85°C; SizeZ_mm: 0.6; SizeX_mm: 1; SizeY_mm: 0.5; CompType: Capacitor; Cap_F: 1µF; AEC Category: Q200
C11 C42 = CMP-0007503-3: CAP, CERM, 4.7 uF, 6.3 V, +/- 10%, X7R, 0603; Manufacturer: Taiyo Yuden; TaMin_C: -55°C; Polarized: N; SizeAreaWB_mm2: 4.68; Value1: Unknown; U/M: EA; Value: 4.7uF; TaMax_C: 125°C; SizeZ_mm: 1; SizeX_mm: 1.6; SizeY_mm: 0.8; SizeArea_mm2: 1.28; Cap_F: 4.7µF; AEC Category: Q200
C22 C47 = CMP-0006678-2: CAP, CERM, 1500 pF, 50 V, +/- 10%, X7R, 0402; Manufacturer: MuRata; TaMin_C: -55°C; Polarized: N; SizeAreaWB_mm2: 3; Value1: Unknown; U/M: EA; Value: 1500pF; TaMax_C: 125°C; SizeZ_mm: 0.6; SizeX_mm: 1; SizeY_mm: 0.5; Cap_F: 1.5nF; AEC Category: Q200
C25 C50 = CMP-0007690-2: CAP, CERM, 4.7 uF, 10 V, +/- 10%, X7R, 0805; Manufacturer: Wurth Elektronik; TaMin_C: -55°C; Polarized: N; SizeAreaWB_mm2: 6.75; Value1: Unknown; U/M: EA; Value: 4.7uF; TaMax_C: 125°C; SizeZ_mm: 1.45; SizeX_mm: 2; SizeY_mm: 1.25; Cap_Case: 0805; SizeArea_mm2: 2.5; Cap_F: 4.7µF; AEC Category: Q200
L1-L6 = CMP-0062881-1: Inductor, Film, 2.2 uH, 2.6 A, 0.084 ohm, AEC-Q200 Grade 0, SMD; Manufacturer: TDK; Isat: 2.8A @ 30% inductance drop; Irms: 2.6A @ 40C rise; Green_Lifecycle: Not Set; SizeAreaWB_mm2: 10.5; DCR_ohm: 0.084; Green_REACh: Incomplete; Value: 2.2uH; SizeZ_mm: 1.2; SizeX_mm: 2.5; SizeY_mm: 2; SizeArea_mm2: 5; Ind_H: 2.2µH; AEC Qualified: Y; AEC Grade: 0; AEC Category: Q200
R1 R30 = CMP-0025963-2: RES, 10.0, 1%, 0.063 W, 0402; Manufacturer: Vishay-Dale; Power_W: 63mW; TempCo: 100 ppm/C; Value_Code: 10R0; U/M: EA; Value: 10.0; EIA_Code: E96; Res_ohm: 10; SizeX_mm: 1; SizeY_mm: 0.5; SizeZ_mm: 0.6; Value2: 0.063W; VDC_V: 50V; AEC Category: Q200
R2 R33 = CMP-0018573-2: RES, 0, 5%, 0.25 W, 1206; Manufacturer: Vishay-Dale; Power_W: 250mW; TempCo: 200 ppm/C; Value_Code: 0000; U/M: EA; Value: 0; EIA_Code: E24; SizeX_mm: 3.2; SizeY_mm: 1.6; SizeZ_mm: 1.35; Value2: 0.25W; SizeArea_mm2: 5.12; VDC_V: 200V; AEC Category: Q200
R3 R4 R31 R32 = CMP-0026952-4: RES, 5.6 k, 5%, 0.063 W, 0402; Manufacturer: Vishay-Dale; Power_W: 63mW; TempCo: 200 ppm/C; Value_Code: 5k60; U/M: EA; Value: 5.6k; EIA_Code: E24; SizeX_mm: 1; SizeY_mm: 0.5; SizeZ_mm: 0.6; Value2: 0.063W; VDC_V: 50V; AEC Category: Q200
R5 R6 R18-R20 R25 R27 R28 R36 R37 R39 R41 R51-R53 R57-R59 = CMP-0026964-2: RES, 68, 5%, 0.063 W, 0402; Manufacturer: Vishay-Dale; Power_W: 63mW; TempCo: 200 ppm/C; Value_Code: 68R0; U/M: EA; Value: 68; EIA_Code: E24; SizeX_mm: 1; SizeY_mm: 0.5; SizeZ_mm: 0.6; Value2: 0.063W; VDC_V: 50V; AEC Category: Q200
R7 = CMP-0025959-2: RES, 10.2 k, 1%, 0.063 W, 0402; Manufacturer: Vishay-Dale; Power_W: 63mW; TempCo: 100 ppm/C; Value_Code: 10k2; U/M: EA; Value: 10.2k; EIA_Code: E96; SizeX_mm: 1; SizeY_mm: 0.5; SizeZ_mm: 0.6; Value2: 0.063W; VDC_V: 50V; AEC Category: Q200
R8 R10 R38 R43 = CMP-0026823-2: RES, 100 k, 5%, 0.063 W, 0402; Manufacturer: Vishay-Dale; Power_W: 63mW; TempCo: 200 ppm/C; U/M: EA; Value: 100k; EIA_Code: E24; SizeX_mm: 1; SizeY_mm: 0.5; SizeZ_mm: 0.6; Value2: 0.063W; VDC_V: 50V; AEC Category: Q200
R9 R15 R22 R23 R26 R35 R42 R48 R55 = CMP-0026815-1: RES, 100 k, 0.1%, 0.063 W, 0402; Manufacturer: Susumu Co Ltd; Power_W: 63mW; TempCo: 25 ppm/C; U/M: EA; Value: 100k; EIA_Code: E192; SizeX_mm: 1; SizeY_mm: 0.5; SizeZ_mm: 0.6; Value2: 0.063W; AEC Category: Q200
R11-R14 R44-R47 = CMP-0026825-4: RES, 10 k, 5%, 0.063 W, 0402; Manufacturer: Vishay-Dale; Power_W: 63mW; TempCo: 200 ppm/C; Value_Code: 10k0; U/M: EA; Value: 10k; EIA_Code: E24; SizeX_mm: 1; SizeY_mm: 0.5; SizeZ_mm: 0.6; Value2: 0.063W; VDC_V: 50V; AEC Category: Q200
R16 R49 R54 = CMP-0026158-1: RES, 200 k, 1%, 0.063 W, 0402; Manufacturer: Vishay-Dale; Power_W: 63mW; TempCo: 100 ppm/C; U/M: EA; Value: 200k; EIA_Code: E96; SizeX_mm: 1; SizeY_mm: 0.5; SizeZ_mm: 0.6; Value2: 0.063W; VDC_V: 50V; AEC Category: Q200
R17 = CMP-0026176-1: RES, 226 k, 1%, 0.063 W, 0402; Manufacturer: Vishay-Dale; Power_W: 63mW; TempCo: 100 ppm/C; U/M: EA; Value: 226k; EIA_Code: E96; SizeX_mm: 1; SizeY_mm: 0.5; SizeZ_mm: 0.6; Value2: 0.063W; VDC_V: 50V; AEC Category: Q200
R21 = CMP-0026288-1: RES, 316 k, 1%, 0.063 W, 0402; Manufacturer: Vishay-Dale; Power_W: 63mW; TempCo: 100 ppm/C; U/M: EA; Value: 316k; EIA_Code: E96; SizeX_mm: 1; SizeY_mm: 0.5; SizeZ_mm: 0.6; Value2: 0.063W; VDC_V: 50V; AEC Category: Q200
R24 = CMP-0026702-1: RES, 49.9 k, 1%, 0.1 W, AEC-Q200 Grade 0, 0402; Manufacturer: Panasonic; Power_W: 100mW; TempCo: 100 ppm/C; Value_Code: 49k9; U/M: EA; Value: 49.9k; EIA_Code: E96; SizeX_mm: 1; SizeY_mm: 0.5; SizeZ_mm: 0.6; Value2: 0.1W; AEC Qualified: Y; VDC_V: 50V; AEC Grade: 0; AEC Category: Q200
R29 = CMP-0026822-2: RES, 0, 5%, 0.063 W, 0402; Manufacturer: Vishay-Dale; Power_W: 63mW; TempCo: 200 ppm/C; Value_Code: 0000; U/M: EA; Value: 0; EIA_Code: E24; SizeX_mm: 1; SizeY_mm: 0.5; SizeZ_mm: 0.6; Value2: 0.063W; VDC_V: 50V; AEC Category: Q200
R34 = CMP-0026196-1: RES, 24.9 k, 1%, 0.063 W, 0402; Manufacturer: Vishay-Dale; Power_W: 63mW; TempCo: 100 ppm/C; Value_Code: 24k9; U/M: EA; Value: 24.9k; EIA_Code: E96; SizeX_mm: 1; SizeY_mm: 0.5; SizeZ_mm: 0.6; Value2: 0.063W; VDC_V: 50V; AEC Category: Q200
R40 = CMP-0026502-1: RES, 66.5 k, 1%, 0.063 W, 0402; Manufacturer: Vishay-Dale; Power_W: 63mW; TempCo: 100 ppm/C; Value_Code: 66k5; U/M: EA; Value: 66.5k; EIA_Code: E96; SizeX_mm: 1; SizeY_mm: 0.5; SizeZ_mm: 0.6; Value2: 0.063W; VDC_V: 50V; AEC Category: Q200
R50 = CMP-0026789-1: RES, 86.6 k, 0.1%, 0.063 W, AEC-Q200 Grade 0, 0402; Manufacturer: Panasonic; Power_W: 63mW; TempCo: 25 ppm/C; Value_Code: 86k6; U/M: EA; Value: 86.6k; EIA_Code: E192; SizeX_mm: 1; SizeY_mm: 0.5; SizeZ_mm: 0.6; Value2: 0.063W; AEC Qualified: Y; VDC_V: 50V; AEC Grade: 0; AEC Category: Q200
R56 = CMP-0026158-1: RES, 200 k, 1%, 0.063 W, 0402; Manufacturer: Vishay-Dale; Power_W: 63mW; TempCo: 100 ppm/C; U/M: EA; Value: 200k; EIA_Code: E96; SizeX_mm: 1; SizeY_mm: 0.5; SizeZ_mm: 0.6; Value2: 0.063W; CompType: Resistor; VDC_V: 50V; AEC Category: Q200
S1 S2 = CMP-0002132-2: Switch, Tactile, SPST-NO, SMT; Manufacturer: C&K Components; CurrentRating_mA: 50A; PositionCount: 1; VDC_V: 32V; SwitchFunction: Off-Mom
U1 U3 = CMP-0074190-1: 6-channel Power Management IC (PMIC) with 3DC/DCs, 3 LDOs, I2C Interface and DVS, RSB0040B (WQFN-40); Alternate PartNumber: TPS65023BRSBT; Alternate Manufacturer: Texas Instruments; SizeAreaWB_mm2: 49.0; U/M: EA; SizeZ_mm: 0.8; SizeX_mm: 5.0; SizeArea_mm2: 25.0
U2 U4 = CMP-0066647-2: 3.6V, 4A, 5.3mΩ Load Switch with Quick Output Discharge, YZP0008ADCD (DSBGA-8); Alternate PartNumber: TPS22920YZPT; Alternate Manufacturer: Texas Instruments; Green_Lifecycle: Active; SizeAreaWB_mm2: 7.3125; Green_REACh: Passed; U/M: EA; SizeZ_mm: 0.5; SizeX_mm: 1.25; SizeY_mm: 2.25; SizeArea_mm2: 2.8125; CompType: IC

## Sheet TIDA01480_pg5_OutPwrRails.SchDoc
size 431 x 279 mm; Date: Not shown in title block; ApprovedBy: Not shown in title block; CheckedBy: Not shown in title block; Author: Not shown in title block; CompanyName: Not shown in title block; Engineer: Not shown in title block; Organization: Not shown in title block; Address1: Not shown in title block; Address2: Not shown in title block; Address3: Not shown in title block; Address4: Not shown in title block; DocumentNumber: 1; Revision: Use project parameter SCH_Rev; SheetNumber: 5; SheetTotal: 7; PageSetup: Record=PageOptions¦CenterHorizontal=True¦CenterVertical=True¦PrintScale=1.00¦XCorrection=1.00¦YCorrection=1.00¦PrintKind=0¦BorderSize=5000000¦LeftOffset=0¦BottomOffset=0¦Orientation=2¦PaperLength=1000¦PaperWidth=1000¦Scale=100¦PaperSource=15¦PrintQuality=600¦MediaType=1¦DitherType=10¦PaperKind=Letter¦PrintScaleMode=1
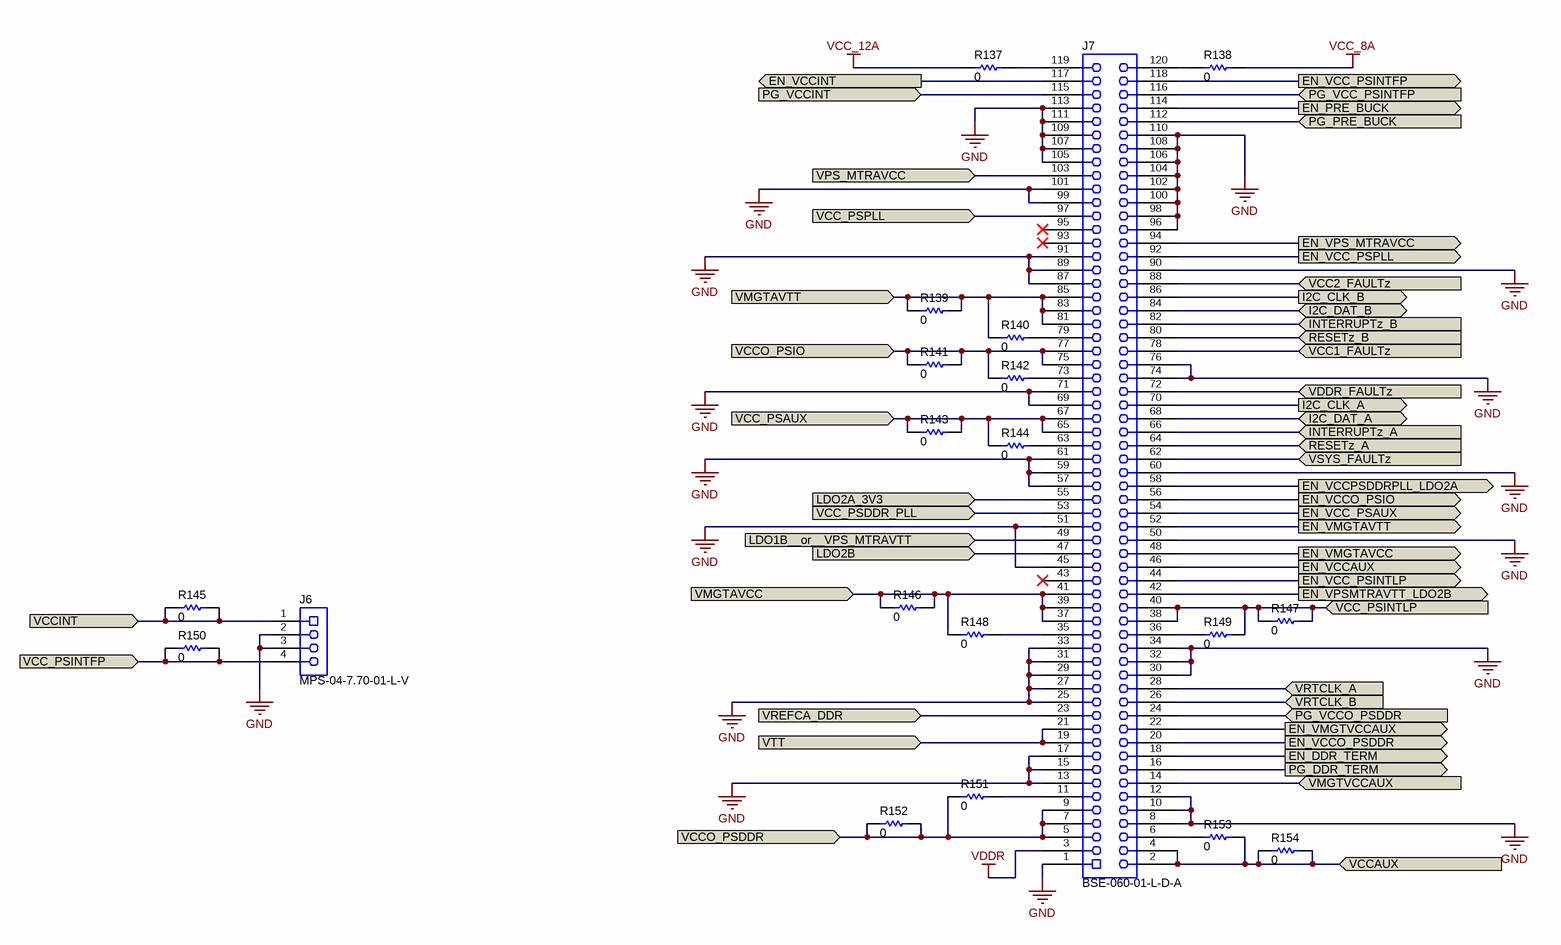
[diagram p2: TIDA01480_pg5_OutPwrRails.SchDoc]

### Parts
J6  MPS-04-7.70-01-L-V  [Samtec_MPS-04-7_70-01-x-V]
J7  BSE-060-01-L-D-A  [Samtec_BSE-060-01-L-D-A]
R137  ValueDisplayed: 0  [0201]  (hidden comment: CRCW02010000Z0ED)
R138  ValueDisplayed: 0  [0201]  (hidden comment: CRCW02010000Z0ED)
R139  ValueDisplayed: 0  [0201]  (hidden comment: CRCW02010000Z0ED)
R140  ValueDisplayed: 0  [0201]  (hidden comment: CRCW02010000Z0ED)
R141  ValueDisplayed: 0  [0201]  (hidden comment: CRCW02010000Z0ED)
R142  ValueDisplayed: 0  [0201]  (hidden comment: CRCW02010000Z0ED)
R143  ValueDisplayed: 0  [0201]  (hidden comment: CRCW02010000Z0ED)
R144  ValueDisplayed: 0  [0201]  (hidden comment: CRCW02010000Z0ED)
R145  ValueDisplayed: 0  [0201]  (hidden comment: CRCW02010000Z0ED)
R146  ValueDisplayed: 0  [0201]  (hidden comment: CRCW02010000Z0ED)
R147  ValueDisplayed: 0  [0201]  (hidden comment: CRCW02010000Z0ED)
R148  ValueDisplayed: 0  [0201]  (hidden comment: CRCW02010000Z0ED)
R149  ValueDisplayed: 0  [0201]  (hidden comment: CRCW02010000Z0ED)
R150  ValueDisplayed: 0  [0201]  (hidden comment: CRCW02010000Z0ED)
R151  ValueDisplayed: 0  [0201]  (hidden comment: CRCW02010000Z0ED)
R152  ValueDisplayed: 0  [0201]  (hidden comment: CRCW02010000Z0ED)
R153  ValueDisplayed: 0  [0201]  (hidden comment: CRCW02010000Z0ED)
R154  ValueDisplayed: 0  [0201]  (hidden comment: CRCW02010000Z0ED)

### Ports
EN_DDR_TERM (out), EN_PRE_BUCK (out), EN_VCC_PSAUX (out), EN_VCC_PSINTFP (out), EN_VCC_PSINTLP (out), EN_VCC_PSPLL (out), EN_VCCAUX (out), EN_VCCINT (out), EN_VCCO_PSDDR (out), EN_VCCO_PSIO (out), EN_VCCPSDDRPLL_LDO2A (out), EN_VMGTAVCC (out), EN_VMGTAVTT (out), EN_VMGTVCCAUX (out), EN_VPS_MTRAVCC (out), EN_VPSMTRAVTT_LDO2B (out), I2C_CLK_A (out), I2C_CLK_B (out), I2C_DAT_A (bidir), I2C_DAT_B (bidir), INTERRUPTz_A (in), INTERRUPTz_B (in), LDO1B__or__VPS_MTRAVTT (in), LDO2A_3V3 (in), LDO2B (in), PG_DDR_TERM (out), PG_PRE_BUCK (in), PG_VCC_PSINTFP (in), PG_VCCINT (in), PG_VCCO_PSDDR (in), RESETz_A (in), RESETz_B (in), VCC1_FAULTz (in), VCC2_FAULTz (in), VCC_PSAUX (in), VCC_PSDDR_PLL (in), VCC_PSINTFP (in), VCC_PSINTLP (in), VCC_PSPLL (in), VCCAUX (in), VCCINT (in), VCCO_PSDDR (in), VCCO_PSIO (in), VDDR_FAULTz (in), VMGTAVCC (in), VMGTAVTT (in), VMGTVCCAUX (in), VPS_MTRAVCC (in), VREFCA_DDR (in), VRTCLK_A (in), VRTCLK_B (in), VSYS_FAULTz (in), VTT (in)

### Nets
GND: J6.2 J6.3 J7.1 J7.8 J7.10 J7.12 J7.13 J7.15 J7.17 J7.25 J7.27 J7.29 J7.30 J7.31 J7.32 J7.33 J7.34 J7.45 J7.50 J7.51 J7.57 J7.59 J7.60 J7.61 J7.69 J7.71 J7.74 J7.76 J7.87 J7.89 J7.90 J7.91 J7.96 J7.98 J7.99 J7.100 J7.101 J7.102 J7.104 J7.105 J7.106 J7.107 J7.108 J7.109 J7.110 J7.111 J7.113
VCC_1or2A: J7.5 J7.7 J7.9 R151.1 R152.1 R152.2 ; port VCCO_PSDDR
VCC_8A: J6.4 R138.2 R150.1 R150.2 ; port VCC_PSINTFP
VCC_12A: J6.1 R137.1 R145.1 R145.2 ; port VCCINT
VDCDC1_A: J7.81 J7.83 J7.85 R139.1 R139.2 R140.1 ; port VMGTAVTT
VDCDC1_B: J7.37 J7.39 J7.41 R146.1 R146.2 R148.1 ; port VMGTAVCC
VDCDC2_A: J7.65 J7.67 R143.1 R143.2 R144.1 ; port VCC_PSAUX
VDCDC2_B: J7.2 J7.4 R153.2 R154.1 R154.2 ; port VCCAUX
VDCDC3_A: J7.75 J7.77 R141.1 R141.2 R142.1 ; port VCCO_PSIO
VDCDC3_B: J7.38 J7.40 R147.1 R147.2 R149.2 ; port VCC_PSINTLP
VDDR: J7.3
VLDO1A_1V8: J7.53 ; port VCC_PSDDR_PLL
VLDO2A_3V3: J7.55 ; port LDO2A_3V3
BUCK_1or2A_EN: J7.20 ; port EN_VCCO_PSDDR
BUCK_8A_EN: J7.118 ; port EN_VCC_PSINTFP
BUCK_12A_EN: J7.117 ; port EN_VCCINT
DCDC1_EN_A: J7.52 ; port EN_VMGTAVTT
DCDC1_EN_B: J7.48 ; port EN_VMGTAVCC
DCDC2_EN_A: J7.54 ; port EN_VCC_PSAUX
DCDC2_EN_B: J7.46 ; port EN_VCCAUX
DCDC3_EN_A: J7.56 ; port EN_VCCO_PSIO
DCDC3_EN_B: J7.44 ; port EN_VCC_PSINTLP
DDR_Strt_PG: J7.24 ; port PG_VCCO_PSDDR
DDR_TT_PG: J7.16 ; port PG_DDR_TERM
EN_DDR_TERM: J7.18 ; port EN_DDR_TERM
EN_PRE_BUCK: J7.114 ; port EN_PRE_BUCK
EN_SEQ_LDOA: J7.58 ; port EN_VCCPSDDRPLL_LDO2A
EN_SEQ_LDOB: J7.42 ; port EN_VPSMTRAVTT_LDO2B
EN_SEQ_LS1: J7.92 ; port EN_VCC_PSPLL
EN_SEQ_LS2: J7.22 ; port EN_VMGTVCCAUX
EN_SEQ_LS3: J7.94 ; port EN_VPS_MTRAVCC
HiCurrent_PG: J7.115 ; port PG_VCCINT
HV_AIC_PG: J7.112 ; port PG_PRE_BUCK
I2C_CLK_A: J7.70 ; port I2C_CLK_A
I2C_CLK_B: J7.86 ; port I2C_CLK_B
I2C_DAT_A: J7.68 ; port I2C_DAT_A
I2C_DAT_B: J7.84 ; port I2C_DAT_B
INTERRUPTz_A: J7.66 ; port INTERRUPTz_A
INTERRUPTz_B: J7.82 ; port INTERRUPTz_B
LDO1B__or__VPS_MTRAVTT: J7.49 ; port LDO1B__or__VPS_MTRAVTT
LDO2B: J7.47 ; port LDO2B
LOW_BATz_A: J7.62 ; port VSYS_FAULTz
LOW_BATz_B: J7.78 ; port VCC1_FAULTz
MidCurrent_PG: J7.116 ; port PG_VCC_PSINTFP
PWRFAILz_A: J7.72 ; port VDDR_FAULTz
PWRFAILz_B: J7.88 ; port VCC2_FAULTz
RESETz_A: J7.64 ; port RESETz_A
RESETz_B: J7.80 ; port RESETz_B
VCC_12A_LS3: J7.103 ; port VPS_MTRAVCC
VCC_PSPLL: J7.97 ; port VCC_PSPLL
VDCDC2_B_LS2: J7.14 ; port VMGTVCCAUX
VREFCA_DDR: J7.23 ; port VREFCA_DDR
VRTC_A: J7.28 ; port VRTCLK_A
VRTC_B: J7.26 ; port VRTCLK_B
VTT: J7.19 J7.21 ; port VTT
NetJ7_6: J7.6 R153.1
NetJ7_11: J7.11 R151.2
NetJ7_35: J7.35 R148.2
NetJ7_36: J7.36 R149.1
NetJ7_63: J7.63 R144.2
NetJ7_73: J7.73 R142.2
NetJ7_79: J7.79 R140.2
NetJ7_119: J7.119 R137.2
NetJ7_120: J7.120 R138.1

Not connected (* = marked no-connect by the designer): J7 43* 93* 95*

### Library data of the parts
J6 = CMP-0078461-1: Receptacle, 5mm, 4x1, Gold with Tin tail, TH; Manufacturer: Samtec; Pitch_mm: 5; Gender: Female; Cert_UL: Y; Voltage_V: 812V; Current_A: 30A; Row_Count: 1; CompType: Socket Strip
J7 = CMP-0078459-1: Socket Assembly, 0.8mm, 60x2, Gold, SMT; Manufacturer: Samtec; Pitch_mm: 0.8; Gender: Female; Cert_UL: Y; Row_Count: 2; CompType: Socket Strip
R137-R154 = CMP-0027008-3: RES, 0, 5%, 0.05 W, 0201; Manufacturer: Vishay-Dale; Power_W: 50mW; TempCo: ppm/C; Value_Code: 0000; U/M: EA; Value: 0; EIA_Code: E24; SizeX_mm: 0.6; SizeY_mm: 0.3; SizeZ_mm: 0.26; Value2: 0.05W; SizeArea_mm2: 0.18; AEC Qualified: N; AEC Category: Q200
